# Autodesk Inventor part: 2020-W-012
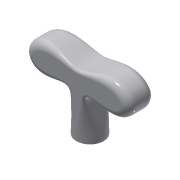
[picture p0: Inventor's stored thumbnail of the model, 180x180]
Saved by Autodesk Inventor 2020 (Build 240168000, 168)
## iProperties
Created: 2013-12
Part Number: 2020-W-012
Material: Ogólny
Document SubType Name: Modeling
Designer: F.Stasiak
Density: 1 g/cm^3
Appearance: Biały
Manager: www.cadconsulting.pl
Company: Fabian Stasiak CAD Consulting
Author: F.Stasiak
Subject: Zbiór ćwiczeń. Autodesk Inventor 2020. Kurs podstawowy
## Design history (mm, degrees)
sketch "Szkic1"
  geometry: L1 (0, 0)-(0, 45); L2 (0, 0)-(-10, 0); L3 (-10, 0)-(-10, 31); L4 (-10, 31)-(-35, 31); L5 (-35, 31)-(-35, 45); L6 (-35, 45)-(0, 45); L7 (-9.282, 45)-(9.282, 45); L8 (-10, -13.923)-(-10, 13.923); L9 (-40.505, 39.495)-(-29.495, 50.505); L10 (-29.403, 25.403)-(-40.597, 36.597); A1 r 12.313 centre (0, 57.313) between (-6.359, 46.769) and (6.359, 46.769); A2 r 25.573 centre (15.573, 0) between (-7.873, 10.212) and (-7.873, -10.212); A3 r 13.272 centre (-25.615, 35.615) between (-30.124, 48.098) and (-38.098, 40.124); A4 r 11.284 centre (-27.021, 38.979) between (-37.884, 35.926) and (-30.074, 28.116)
  constraints: 20 end point, 8 midpoint, 4 centre point, 4 perpendicular, 4 point on circle, 3 vertical, 2 horizontal, 1 parallel, 11 other
  dimensions: "d1" = 10 distance of L1.start L2.end; "d2" = 35 distance between parallel lines of L1 L5; "d3" = 14 distance of L4.end L5.end; "d4" = 45 distance of L1.start L1.end; "d20" = 10 dimension on L7.start L7.end; "d21" = 45 deg angle of L9 L6; "d22" = 45 deg angle of L10 L4; "d32" = 15 dimension on L8.start L8.end
extrude "Wyciągnięcie proste1" new body sketch "Szkic1" distance "d6" = 10; taper "d7" = 0 deg
fillet "Zaokrąglenie2" dims "d23" = 2, "d24" = 10, "d25" = 2, "d26" = 7.845, "d27" = 6, "d28" = 3.753
mirror "Odbicie lustrzane2"
mirror "Odbicie lustrzane3"
sketch "Szkic2"
  geometry: L1 (10.036, -2.036)-(10.036, -10.036); L2 (10.036, -10.036)-(2.036, -10.036); L3 (2.036, -10.036)-(2.036, -2.036); L4 (2.036, -2.036)-(10.036, -2.036); 2 further points
  constraints: 8 end point, 1 coincident, 9 other
  dimensions: "d29" = 8 distance of L1.start L1.end
extrude "Wyciągnięcie proste2" cut sketch "Szkic2" distance "d30" = 15; taper "d31" = 0 deg
node "Bryła1"
